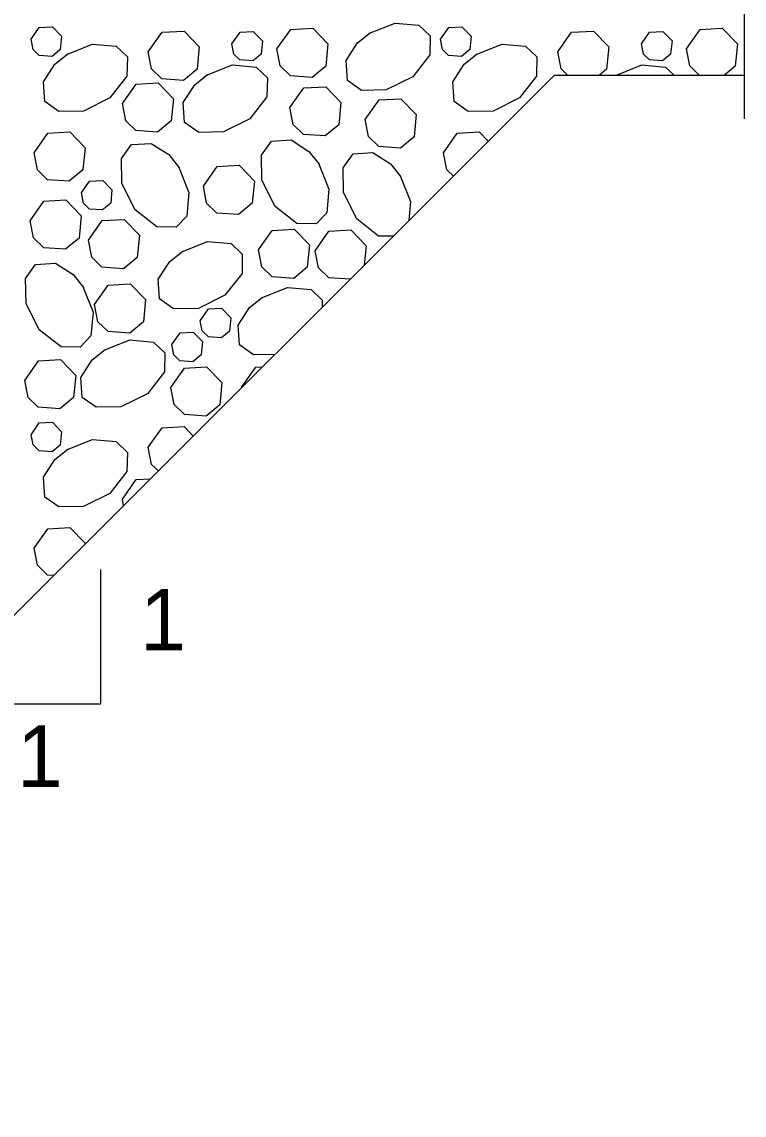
# Model space of a CAD drawing. Extents: x 2084213 to 2099800, y 976677 to 981262.
# Drawn here: x 2095383.7 to 2095499.4, y 979031.7 to 979206.9 of the extents above; entities that cross this region are included whole.
import ezdxf

# ---------------------------------------------------------------- set-up
doc = ezdxf.new("R2010")
doc.units = 0
doc.layers.add('1', color=7, linetype='Continuous')

msp = doc.modelspace()

# ---------------------------------------------------------------- linework, layer by layer
at = {"layer": '1'}
for p, q in [((2095499.4, 979282.52), (2095499.4, 979191.31)), ((2095302.37, 979031.66), (2095469.04, 979198.33)), ((2095302.38, 979031.67), (2095469.04, 979198.33)), ((2095469.04, 979198.33), (2095499.41, 979198.33)), ((2095396.33, 979119.11), (2095396.33, 979097.51)), ((2095396.33, 979097.51), (2095374.73, 979097.51))]:
    msp.add_line(p, q, dxfattribs=at)
for points in [[(2095385.21, 979204.06), (2095386.53, 979205.94), (2095388.64, 979206.06), (2095390.11, 979204.54), (2095389.9, 979202.41), (2095388.59, 979201.32), (2095386.51, 979201.47), (2095385.53, 979202.43), (2095385.21, 979204.06)], [(2095424.6, 979202.52), (2095426.81, 979205.66), (2095430.33, 979205.86), (2095432.77, 979203.33), (2095432.42, 979199.77), (2095430.25, 979197.96), (2095426.77, 979198.21), (2095425.13, 979199.8), (2095424.6, 979202.52)], [(2095439.4, 979205.03), (2095443.53, 979206.67), (2095447.32, 979206.34), (2095449.12, 979204.63), (2095449.06, 979201.55), (2095446.33, 979198.06), (2095442.1, 979195.94), (2095438.12, 979195.88), (2095435.88, 979197.47), (2095435.67, 979200.64), (2095437.48, 979203.48), (2095439.57, 979205.14)], [(2095450.79, 979204.06), (2095452.11, 979205.94), (2095454.22, 979206.06), (2095455.69, 979204.54), (2095455.48, 979202.41), (2095454.17, 979201.32), (2095452.09, 979201.47), (2095451.11, 979202.43), (2095450.79, 979204.06)], [(2095490.18, 979202.52), (2095492.38, 979205.66), (2095495.91, 979205.86), (2095498.35, 979203.33), (2095498, 979199.77), (2095496.27, 979198.33)], [(2095403.99, 979202.05), (2095406.2, 979205.19), (2095409.72, 979205.39), (2095412.16, 979202.85), (2095411.81, 979199.29), (2095409.64, 979197.48), (2095406.16, 979197.73), (2095404.52, 979199.32), (2095403.99, 979202.05)], [(2095417.37, 979203.34), (2095418.7, 979205.22), (2095420.81, 979205.34), (2095422.28, 979203.82), (2095422.06, 979201.68), (2095420.76, 979200.6), (2095418.67, 979200.75), (2095417.69, 979201.7), (2095417.37, 979203.34)], [(2095469.57, 979202.05), (2095471.77, 979205.19), (2095475.29, 979205.39), (2095477.74, 979202.85), (2095477.39, 979199.29), (2095476.23, 979198.33)], [(2095482.95, 979203.34), (2095484.27, 979205.22), (2095486.39, 979205.34), (2095487.86, 979203.82), (2095487.64, 979201.68), (2095486.34, 979200.6), (2095484.25, 979200.75), (2095483.27, 979201.7), (2095482.95, 979203.34)], [(2095390.92, 979201.65), (2095395.05, 979203.28), (2095398.84, 979202.95), (2095400.64, 979201.24), (2095400.58, 979198.17), (2095397.85, 979194.67), (2095393.62, 979192.56), (2095389.64, 979192.49), (2095387.4, 979194.08), (2095387.19, 979197.25), (2095389.01, 979200.09), (2095391.09, 979201.75)], [(2095456.5, 979201.65), (2095460.63, 979203.28), (2095464.42, 979202.95), (2095466.22, 979201.24), (2095466.16, 979198.17), (2095463.43, 979194.67), (2095459.2, 979192.56), (2095455.22, 979192.49), (2095452.98, 979194.08), (2095452.77, 979197.25), (2095454.58, 979200.09), (2095456.67, 979201.75)], [(2095492.23, 979198.33), (2095490.71, 979199.8), (2095490.18, 979202.52)], [(2095471.12, 979198.33), (2095470.1, 979199.32), (2095469.57, 979202.05)], [(2095413.34, 979198.31), (2095417.46, 979199.95), (2095421.25, 979199.62), (2095423.06, 979197.91), (2095423, 979194.83), (2095420.26, 979191.34), (2095416.04, 979189.22), (2095412.06, 979189.15), (2095409.81, 979190.74), (2095409.6, 979193.92), (2095411.42, 979196.75), (2095413.5, 979198.42)], [(2095478.96, 979198.33), (2095483.04, 979199.95), (2095486.83, 979199.62), (2095488.19, 979198.33)], [(2095399.84, 979193.75), (2095402.05, 979196.88), (2095405.57, 979197.09), (2095408.01, 979194.55), (2095407.66, 979190.99), (2095405.48, 979189.18), (2095402.01, 979189.43), (2095400.37, 979191.02), (2095399.84, 979193.75)], [(2095478.96, 979198.33), (2095479.07, 979198.42)], [(2095478.97, 979198.33), (2095479.08, 979198.42)], [(2095426.68, 979193.13), (2095428.88, 979196.27), (2095432.4, 979196.47), (2095434.85, 979193.93), (2095434.5, 979190.38), (2095432.32, 979188.57), (2095428.84, 979188.82), (2095427.21, 979190.4), (2095426.68, 979193.13)], [(2095438.73, 979191.21), (2095440.94, 979194.35), (2095444.46, 979194.55), (2095446.91, 979192.01), (2095446.55, 979188.45), (2095444.38, 979186.64), (2095440.9, 979186.9), (2095439.27, 979188.48), (2095438.74, 979191.21)], [(2095385.69, 979185.87), (2095387.9, 979189.01), (2095391.42, 979189.21), (2095393.87, 979186.67), (2095393.52, 979183.12), (2095391.34, 979181.31), (2095387.86, 979181.56), (2095386.23, 979183.15), (2095385.7, 979185.87)], [(2095451.27, 979185.87), (2095453.48, 979189.01), (2095457, 979189.21), (2095458.44, 979187.72)], [(2095408.85, 979183.66), (2095410.48, 979179.53), (2095410.16, 979175.74), (2095408.44, 979173.94), (2095405.37, 979174), (2095401.87, 979176.73), (2095399.76, 979180.96), (2095399.69, 979184.94), (2095401.28, 979187.18), (2095404.46, 979187.39), (2095407.29, 979185.58), (2095408.95, 979183.49)], [(2095431.27, 979184.19), (2095432.9, 979180.07), (2095432.57, 979176.28), (2095430.86, 979174.48), (2095427.78, 979174.53), (2095424.29, 979177.27), (2095422.18, 979181.49), (2095422.11, 979185.47), (2095423.7, 979187.72), (2095426.87, 979187.93), (2095429.71, 979186.11), (2095431.37, 979184.03)], [(2095443.2, 979172.49), (2095440.86, 979172.53), (2095437.37, 979175.27), (2095435.26, 979179.49), (2095435.18, 979183.47), (2095436.78, 979185.72), (2095439.95, 979185.93), (2095442.79, 979184.11), (2095444.45, 979182.03)], [(2095452.85, 979182.14), (2095451.81, 979183.15), (2095451.28, 979185.87)], [(2095412.81, 979180.54), (2095415.02, 979183.68), (2095418.54, 979183.88), (2095420.99, 979181.34), (2095420.63, 979177.78), (2095418.46, 979175.97), (2095414.98, 979176.22), (2095413.34, 979177.81), (2095412.81, 979180.54)], [(2095393.27, 979179.45), (2095394.6, 979181.33), (2095396.71, 979181.45), (2095398.18, 979179.93), (2095397.97, 979177.79), (2095396.66, 979176.71), (2095394.57, 979176.86), (2095393.59, 979177.81), (2095393.28, 979179.45)], [(2095444.34, 979182.19), (2095445.98, 979178.07), (2095445.71, 979175)], [(2095385.08, 979174.98), (2095387.28, 979178.12), (2095390.8, 979178.32), (2095393.25, 979175.78), (2095392.9, 979172.22), (2095390.72, 979170.41), (2095387.25, 979170.67), (2095385.61, 979172.25), (2095385.08, 979174.98)], [(2095394.4, 979171.87), (2095396.6, 979175), (2095400.12, 979175.2), (2095402.57, 979172.67), (2095402.22, 979169.11), (2095400.04, 979167.3), (2095396.57, 979167.55), (2095394.93, 979169.14), (2095394.4, 979171.86)], [(2095421.64, 979170.31), (2095423.84, 979173.45), (2095427.36, 979173.65), (2095429.81, 979171.11), (2095429.46, 979167.55), (2095427.28, 979165.74), (2095423.81, 979166), (2095422.17, 979167.58), (2095421.64, 979170.31)], [(2095430.71, 979170.18), (2095432.92, 979173.31), (2095436.44, 979173.52), (2095438.89, 979170.98), (2095438.58, 979167.86)], [(2095409.34, 979170.02), (2095413.46, 979171.66), (2095417.25, 979171.33), (2095419.05, 979169.62), (2095419, 979166.54), (2095416.26, 979163.05), (2095412.04, 979160.93), (2095408.05, 979160.86), (2095405.81, 979162.46), (2095405.6, 979165.63), (2095407.42, 979168.47), (2095409.5, 979170.13)], [(2095436.33, 979165.61), (2095432.88, 979165.86), (2095431.24, 979167.45), (2095430.71, 979170.18)], [(2095393.5, 979164.45), (2095395.14, 979160.32), (2095394.81, 979156.53), (2095393.1, 979154.73), (2095390.02, 979154.79), (2095386.53, 979157.52), (2095384.42, 979161.74), (2095384.35, 979165.73), (2095385.94, 979167.97), (2095389.11, 979168.18), (2095391.95, 979166.36), (2095393.61, 979164.28)], [(2095395.38, 979161.54), (2095397.58, 979164.68), (2095401.11, 979164.88), (2095403.55, 979162.34), (2095403.2, 979158.79), (2095401.02, 979156.98), (2095397.55, 979157.23), (2095395.91, 979158.81), (2095395.38, 979161.54)], [(2095422.14, 979162.65), (2095426.26, 979164.29), (2095430.05, 979163.96), (2095431.85, 979162.25), (2095431.83, 979161.12)], [(2095424.27, 979153.55), (2095420.86, 979153.49), (2095418.61, 979155.09), (2095418.4, 979158.26), (2095420.22, 979161.1), (2095422.3, 979162.76)], [(2095412.3, 979158.97), (2095413.63, 979160.85), (2095415.74, 979160.97), (2095417.21, 979159.45), (2095417, 979157.31), (2095415.69, 979156.23), (2095413.61, 979156.38), (2095412.62, 979157.33), (2095412.31, 979158.97)], [(2095407.75, 979155.14), (2095409.08, 979157.02), (2095411.19, 979157.14), (2095412.66, 979155.62), (2095412.45, 979153.49), (2095411.14, 979152.4), (2095409.05, 979152.55), (2095408.07, 979153.5), (2095407.76, 979155.14)], [(2095396.92, 979154.25), (2095401.05, 979155.88), (2095404.84, 979155.55), (2095406.64, 979153.84), (2095406.58, 979150.77), (2095403.85, 979147.27), (2095399.62, 979145.16), (2095395.64, 979145.09), (2095393.4, 979146.68), (2095393.19, 979149.85), (2095395, 979152.69), (2095397.09, 979154.35)], [(2095384.2, 979149.41), (2095386.41, 979152.55), (2095389.93, 979152.75), (2095392.38, 979150.21), (2095392.02, 979146.65), (2095389.85, 979144.84), (2095386.37, 979145.1), (2095384.73, 979146.68), (2095384.2, 979149.41)], [(2095407.61, 979148.25), (2095409.81, 979151.38), (2095413.33, 979151.58), (2095415.78, 979149.05), (2095415.43, 979145.49), (2095413.25, 979143.68), (2095409.77, 979143.93), (2095408.14, 979145.52), (2095407.61, 979148.24)], [(2095418.99, 979148.38), (2095421.19, 979151.51), (2095422.29, 979151.58)], [(2095419, 979148.29), (2095418.99, 979148.37)], [(2095385.21, 979140.69), (2095386.53, 979142.58), (2095388.64, 979142.7), (2095390.11, 979141.17), (2095389.9, 979139.04), (2095388.59, 979137.95), (2095386.51, 979138.11), (2095385.53, 979139.06), (2095385.21, 979140.69)], [(2095403.99, 979138.68), (2095406.2, 979141.82), (2095409.72, 979142.02), (2095411.2, 979140.48)], [(2095390.92, 979138.28), (2095395.05, 979139.91), (2095398.84, 979139.59), (2095400.64, 979137.87), (2095400.58, 979134.8), (2095397.85, 979131.3), (2095393.62, 979129.19), (2095389.64, 979129.12), (2095387.4, 979130.71), (2095387.19, 979133.88), (2095389.01, 979136.72), (2095391.09, 979138.38)], [(2095405.61, 979134.9), (2095404.52, 979135.95), (2095403.99, 979138.68)], [(2095399.84, 979130.38), (2095402.05, 979133.52), (2095404.36, 979133.65)], [(2095400.04, 979129.33), (2095399.84, 979130.38)], [(2095385.69, 979122.51), (2095387.9, 979125.64), (2095391.42, 979125.84), (2095393.87, 979123.31), (2095393.85, 979123.14)], [(2095388.84, 979118.12), (2095387.86, 979118.19), (2095386.23, 979119.78), (2095385.7, 979122.51)]]:
    msp.add_lwpolyline(points, dxfattribs=at)

# ---------------------------------------------------------------- texts
for p in [(2095402.7, 979106.12), (2095382.96, 979084.26)]:
    msp.add_text('1', height=9.84, dxfattribs=at).set_placement(p)

doc.saveas('drawing.dxf')
